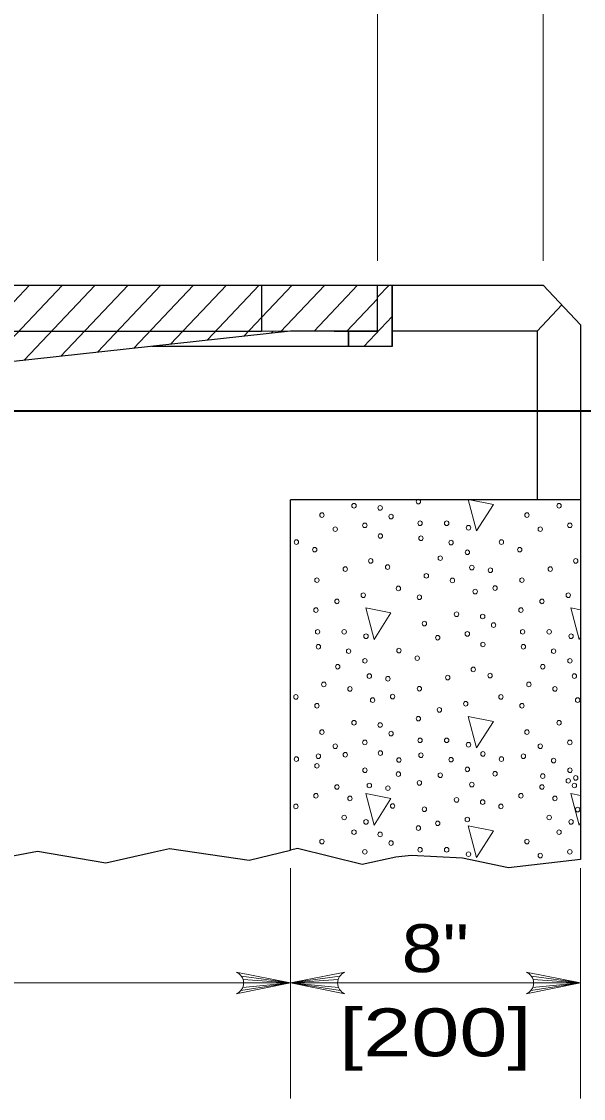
# Model space of a CAD drawing. Extents: x -410.5 to -376.5, y 1617.6 to 1661.6.
# Drawn here: x -402.554 to -400.725, y 1656.08 to 1659.586 of the extents above; entities that cross this region are included whole.
import ezdxf
from ezdxf.enums import TextEntityAlignment as Align

# ---------------------------------------------------------------- set-up
doc = ezdxf.new("R2010")
doc.units = 0
doc.header["$LTSCALE"] = 0.062
doc.layers.add('1', color=7, linetype='Continuous', lineweight=13)

msp = doc.modelspace()

# ---------------------------------------------------------------- linework, layer by layer
at = {"layer": '1'}
for p, q in [((-401.39508, 1658.80683), (-401.39508, 1659.92217)), ((-400.85642, 1658.80683), (-400.85642, 1659.92217)), ((-402.78417, 1658.457), (-402.52817, 1658.72817)), ((-402.66508, 1658.47008), (-402.42133, 1658.72817)), ((-402.54592, 1658.48317), (-402.3145, 1658.72817)), ((-402.42683, 1658.49617), (-402.20775, 1658.72817)), ((-402.30767, 1658.50925), (-402.10092, 1658.72817)), ((-402.18858, 1658.52225), (-401.99408, 1658.72817)), ((-402.06942, 1658.53533), (-401.88733, 1658.72817)), ((-401.95025, 1658.54842), (-401.7805, 1658.72817)), ((-401.89075, 1658.72817), (-401.70192, 1658.72817)), ((-401.83117, 1658.56142), (-401.67375, 1658.72817)), ((-401.71208, 1658.5745), (-401.56692, 1658.72817)), ((-401.60175, 1658.57825), (-401.46008, 1658.72817)), ((-401.39508, 1658.6885), (-401.35767, 1658.72817)), ((-401.49517, 1658.578), (-401.39525, 1658.68375)), ((-401.43975, 1658.52825), (-401.34792, 1658.62542)), ((-401.77275, 1658.57825), (-401.67833, 1658.57825)), ((-401.74208, 1658.57125), (-401.73542, 1658.57825)), ((-401.6825, 1658.57775), (-401.68208, 1658.57825)), ((-400.73442, 1657.6705), (-400.76633, 1657.67675)), ((-400.73433, 1657.06608), (-400.76633, 1657.07225)), ((-401.67833, 1656.07967), (-401.67833, 1656.82983)), ((-400.73433, 1656.07967), (-400.73433, 1656.82983)), ((-401.83858, 1656.47817), (-401.67833, 1656.45575)), ((-401.83308, 1656.46708), (-401.67833, 1656.45575)), ((-401.51808, 1656.47817), (-401.67833, 1656.45575)), ((-401.5235, 1656.46708), (-401.67833, 1656.45575)), ((-400.89458, 1656.47817), (-400.73433, 1656.45575)), ((-400.88908, 1656.46708), (-400.73433, 1656.45575)), ((-404.41592, 1656.45575), (-402.47617, 1656.45575)), ((-402.47617, 1656.45575), (-401.67833, 1656.45575)), ((-401.84042, 1656.43092), (-401.67833, 1656.45575)), ((-401.83433, 1656.44133), (-401.67833, 1656.45575)), ((-401.8315, 1656.45575), (-401.67833, 1656.45575)), ((-401.52517, 1656.45575), (-401.67833, 1656.45575)), ((-401.52233, 1656.44133), (-401.67833, 1656.45575)), ((-401.51617, 1656.43092), (-401.67833, 1656.45575)), ((-400.89642, 1656.43092), (-400.73433, 1656.45575)), ((-400.89033, 1656.44133), (-400.73433, 1656.45575)), ((-400.8875, 1656.45575), (-400.73433, 1656.45575))]:
    msp.add_line(p, q, dxfattribs=at)
at = {"layer": '1', "lineweight": 25}
for p, q in [((-401.77275, 1658.72817), (-401.77275, 1658.57825)), ((-401.39508, 1658.57825), (-401.39508, 1658.72817)), ((-401.39508, 1658.57825), (-401.39508, 1658.72817)), ((-401.34792, 1658.52825), (-401.34792, 1658.72817)), ((-401.30075, 1658.72817), (-400.85642, 1658.72817)), ((-400.73433, 1658.59883), (-400.85642, 1658.72817)), ((-400.87592, 1658.57825), (-400.79533, 1658.6635)), ((-404.3215, 1658.57825), (-401.77275, 1658.57825)), ((-401.39508, 1658.57825), (-401.55542, 1658.57825)), ((-401.4895, 1658.57825), (-401.4895, 1658.52825)), ((-400.87592, 1658.57825), (-401.34983, 1658.57825)), ((-400.87592, 1658.57825), (-400.87592, 1658.0285)), ((-400.73433, 1658.59883), (-400.73433, 1656.858)), ((-401.55542, 1658.52825), (-402.1305, 1658.52825)), ((-401.34792, 1658.52825), (-401.55542, 1658.52825)), ((-400.73433, 1658.0285), (-401.67833, 1658.0285))]:
    msp.add_line(p, q, dxfattribs=at)
at = {"layer": '1', "lineweight": 35}
msp.add_line((-405.89092, 1658.31867), (-400.23342, 1658.31867), dxfattribs=at)
at = {"layer": '1', "lineweight": 25}
for points in [[(-405.23783, 1658.72817), (-404.7935, 1658.72817), (-404.69908, 1658.72817), (-404.3215, 1658.72817), (-401.77275, 1658.72817), (-401.39508, 1658.72817), (-401.30075, 1658.72817)], [(-401.53675, 1658.57825), (-401.39508, 1658.57825), (-401.39508, 1658.72817)], [(-401.53675, 1658.57825), (-401.67833, 1658.57825), (-403.04708, 1658.42833), (-404.41592, 1658.57825), (-404.5575, 1658.57825)], [(-400.73433, 1656.858), (-400.96875, 1656.83008), (-401.11925, 1656.86183), (-401.286, 1656.87042), (-401.33525, 1656.86542), (-401.44525, 1656.8415), (-401.65542, 1656.89367), (-401.67833, 1656.88817), (-401.67833, 1658.0285)], [(-404.41592, 1656.87183), (-404.2725, 1656.83983), (-404.153, 1656.87083), (-403.98442, 1656.85217), (-403.92575, 1656.855), (-403.82517, 1656.88925), (-403.76458, 1656.882), (-403.7105, 1656.87983), (-403.49083, 1656.84083), (-403.33433, 1656.88892), (-403.13075, 1656.86817), (-402.962, 1656.90217), (-402.852, 1656.909), (-402.67125, 1656.85375), (-402.5025, 1656.88475), (-402.27992, 1656.84675), (-402.12158, 1656.88275), (-402.07225, 1656.89375), (-401.81283, 1656.85558), (-401.67833, 1656.88817)]]:
    msp.add_lwpolyline(points, dxfattribs=at)
msp.add_lwpolyline([(-401.4895, 1658.57825), (-401.39508, 1658.57825), (-401.39508, 1658.72817), (-401.34792, 1658.72817), (-401.34792, 1658.52825), (-401.4895, 1658.52825)], close=True, dxfattribs=at)
at = {"layer": '1'}
for points in [[(-401.1, 1658.03008), (-401.07308, 1657.92767), (-401.01817, 1658.01408)], [(-401.43383, 1657.67675), (-401.40683, 1657.57442), (-401.35183, 1657.66083)], [(-401.1, 1657.32342), (-401.07308, 1657.221), (-401.01817, 1657.30742)], [(-401.43383, 1657.07225), (-401.40683, 1656.96983), (-401.35183, 1657.05625)], [(-401.1, 1656.96708), (-401.07308, 1656.86467), (-401.01817, 1656.95117)]]:
    msp.add_lwpolyline(points, close=True, dxfattribs=at)
for points in [[(-400.76633, 1657.67675), (-400.73933, 1657.57442), (-400.73433, 1657.58217)], [(-400.76633, 1657.07225), (-400.73933, 1656.96983), (-400.73433, 1656.97792)], [(-401.85533, 1656.42033), (-401.67833, 1656.45575), (-401.85533, 1656.49108)], [(-401.50133, 1656.42033), (-401.67833, 1656.45575), (-401.50133, 1656.49108)], [(-400.91133, 1656.42033), (-400.73433, 1656.45575), (-400.91133, 1656.49108)], [(-401.67833, 1656.45575), (-400.9465, 1656.45575), (-400.73433, 1656.45575)]]:
    msp.add_lwpolyline(points, dxfattribs=at)
for centre, start, end in [((-401.86959, 1656.45576), 292.08605, 67.91218), ((-401.48701, 1656.45576), 112.08782, 247.91395), ((-400.92559, 1656.45576), 292.08605, 67.91218)]:
    msp.add_arc(centre, 0.0382, start, end, dxfattribs=at)
for centre, major_axis in [((-401.47193, 1658.00974), (0, 0.00756)), ((-401.38687, 1658.00238), (0, 0.00756)), ((-401.26222, 1658.02305), (0, -0.00756)), ((-400.80442, 1658.00974), (0, 0.00756)), ((-401.57645, 1657.97918), (0, 0.00756)), ((-401.35144, 1657.97441), (0, -0.00756)), ((-400.90894, 1657.97918), (0, 0.00756)), ((-401.53317, 1657.93336), (0, 0.00756)), ((-401.43677, 1657.94579), (0, 0.00756)), ((-401.25682, 1657.95244), (0, -0.00756)), ((-401.17027, 1657.95244), (0, 0.00756)), ((-401.09912, 1657.93813), (0, -0.00756)), ((-400.86566, 1657.93336), (0, 0.00756)), ((-400.76926, 1657.94579), (0, 0.00756)), ((-401.65938, 1657.89137), (0, -0.00756)), ((-401.38598, 1657.9111), (0, -0.00756)), ((-401.25415, 1657.9038), (0, -0.00756)), ((-400.99188, 1657.89137), (0, -0.00756)), ((-401.59992, 1657.86658), (0, -0.00756)), ((-401.15586, 1657.88949), (0, 0.00756)), ((-401.10274, 1657.85798), (0, 0.00756)), ((-400.93241, 1657.86658), (0, -0.00756)), ((-401.41752, 1657.83), (0, -0.00756)), ((-401.19107, 1657.8389), (0, 0.00756)), ((-400.75001, 1657.83), (0, -0.00756)), ((-401.50046, 1657.80333), (0, -0.00756)), ((-401.36257, 1657.80998), (0, -0.00756)), ((-401.08827, 1657.80839), (0, 0.00756)), ((-401.02792, 1657.79973), (0, -0.00756)), ((-400.83295, 1657.80333), (0, -0.00756)), ((-401.59269, 1657.76728), (0, -0.00756)), ((-401.23641, 1657.78136), (0, 0.00756)), ((-401.15141, 1657.7664), (0, 0.00756)), ((-400.92518, 1657.76728), (0, -0.00756)), ((-401.44189, 1657.71835), (0, -0.00756)), ((-401.32747, 1657.74031), (0, 0.00756)), ((-401.07754, 1657.73012), (0, 0.00756)), ((-401.01262, 1657.74161), (0, -0.00756)), ((-400.77438, 1657.71835), (0, -0.00756)), ((-401.52755, 1657.69832), (0, -0.00756)), ((-401.25893, 1657.71169), (0, 0.00756)), ((-400.86004, 1657.69832), (0, -0.00756)), ((-401.59597, 1657.6697), (0, -0.00756)), ((-401.13817, 1657.65639), (0, 0.00756)), ((-401.05312, 1657.64903), (0, 0.00756)), ((-400.92846, 1657.6697), (0, -0.00756)), ((-401.24269, 1657.62583), (0, 0.00756)), ((-401.01769, 1657.62106), (0, -0.00756)), ((-401.59058, 1657.59909), (0, -0.00756)), ((-401.50402, 1657.59909), (0, 0.00756)), ((-401.43288, 1657.58478), (0, -0.00756)), ((-401.19942, 1657.58001), (0, 0.00756)), ((-401.10302, 1657.59244), (0, 0.00756)), ((-400.92307, 1657.59909), (0, -0.00756)), ((-400.83651, 1657.59909), (0, 0.00756)), ((-400.76537, 1657.58478), (0, -0.00756)), ((-401.58791, 1657.55045), (0, -0.00756)), ((-401.05223, 1657.55775), (0, -0.00756)), ((-400.9204, 1657.55045), (0, -0.00756)), ((-401.48961, 1657.53614), (0, 0.00756)), ((-401.32563, 1657.53802), (0, -0.00756)), ((-401.26617, 1657.51323), (0, -0.00756)), ((-400.82211, 1657.53614), (0, 0.00756)), ((-401.52483, 1657.48555), (0, 0.00756)), ((-401.43649, 1657.50463), (0, 0.00756)), ((-401.08377, 1657.47665), (0, -0.00756)), ((-400.85732, 1657.48555), (0, 0.00756)), ((-400.76898, 1657.50463), (0, 0.00756)), ((-401.42203, 1657.45504), (0, 0.00756)), ((-401.36168, 1657.44638), (0, -0.00756)), ((-401.16671, 1657.44998), (0, -0.00756)), ((-401.02881, 1657.45663), (0, -0.00756)), ((-400.75452, 1657.45504), (0, 0.00756)), ((-401.57016, 1657.42801), (0, 0.00756)), ((-401.48516, 1657.41305), (0, 0.00756)), ((-401.25893, 1657.41394), (0, -0.00756)), ((-400.90265, 1657.42801), (0, 0.00756)), ((-400.81766, 1657.41305), (0, 0.00756)), ((-401.66122, 1657.38696), (0, 0.00756)), ((-401.41129, 1657.37677), (0, 0.00756)), ((-401.34638, 1657.38826), (0, -0.00756)), ((-401.10813, 1657.365), (0, -0.00756)), ((-400.99371, 1657.38696), (0, 0.00756)), ((-400.74378, 1657.37677), (0, 0.00756)), ((-401.59269, 1657.35834), (0, 0.00756)), ((-401.1938, 1657.34497), (0, -0.00756)), ((-400.92518, 1657.35834), (0, 0.00756)), ((-401.47193, 1657.30304), (0, 0.00756)), ((-401.38687, 1657.29568), (0, 0.00756)), ((-401.26222, 1657.31635), (0, -0.00756)), ((-400.80442, 1657.30304), (0, 0.00756)), ((-401.57645, 1657.27248), (0, 0.00756)), ((-401.35144, 1657.26771), (0, -0.00756)), ((-400.90894, 1657.27248), (0, 0.00756)), ((-401.53317, 1657.22666), (0, 0.00756)), ((-401.43677, 1657.23909), (0, 0.00756)), ((-401.25682, 1657.24574), (0, -0.00756)), ((-401.17027, 1657.24574), (0, 0.00756)), ((-401.09912, 1657.23143), (0, -0.00756)), ((-400.86566, 1657.22666), (0, 0.00756)), ((-400.76926, 1657.23909), (0, 0.00756)), ((-401.58791, 1657.19412), (0, -0.00756)), ((-401.50046, 1657.19882), (0, -0.00756)), ((-401.38598, 1657.2044), (0, -0.00756)), ((-401.25415, 1657.1971), (0, -0.00756)), ((-401.05223, 1657.20143), (0, -0.00756)), ((-400.9204, 1657.19412), (0, -0.00756)), ((-401.65938, 1657.18467), (0, -0.00756)), ((-401.59269, 1657.16278), (0, -0.00756)), ((-401.32563, 1657.1817), (0, -0.00756)), ((-401.15586, 1657.18279), (0, 0.00756)), ((-400.99188, 1657.18467), (0, -0.00756)), ((-400.82211, 1657.17981), (0, 0.00756)), ((-401.43649, 1657.14831), (0, 0.00756)), ((-401.32747, 1657.13581), (0, 0.00756)), ((-401.19107, 1657.1322), (0, 0.00756)), ((-401.10274, 1657.15128), (0, 0.00756)), ((-401.01262, 1657.1371), (0, -0.00756)), ((-400.85732, 1657.12923), (0, 0.00756)), ((-400.76898, 1657.14831), (0, 0.00756)), ((-400.75001, 1657.1233), (0, -0.00756)), ((-401.52755, 1657.09382), (0, -0.00756)), ((-401.42203, 1657.09872), (0, 0.00756)), ((-401.36168, 1657.09006), (0, -0.00756)), ((-401.25894, 1657.10719), (0, 0.00756)), ((-401.08827, 1657.10169), (0, 0.00756)), ((-400.86004, 1657.09382), (0, -0.00756)), ((-400.77438, 1657.11384), (0, -0.00756)), ((-400.75452, 1657.09872), (0, 0.00756)), ((-401.59597, 1657.0652), (0, -0.00756)), ((-401.48517, 1657.05673), (0, 0.00756)), ((-401.13817, 1657.05189), (0, 0.00756)), ((-400.92846, 1657.0652), (0, -0.00756)), ((-400.81766, 1657.05673), (0, 0.00756)), ((-401.66122, 1657.03064), (0, 0.00756)), ((-401.34638, 1657.03194), (0, -0.00756)), ((-401.24269, 1657.02132), (0, 0.00756)), ((-401.05312, 1657.04453), (0, 0.00756)), ((-400.99371, 1657.03064), (0, 0.00756)), ((-400.74379, 1657.02045), (0, 0.00756)), ((-401.50402, 1656.99459), (0, 0.00756)), ((-401.43288, 1656.98028), (0, -0.00756)), ((-401.10302, 1656.98793), (0, 0.00756)), ((-400.83651, 1656.99459), (0, 0.00756)), ((-400.76537, 1656.98028), (0, -0.00756)), ((-401.47193, 1656.94672), (0, 0.00756)), ((-401.26222, 1656.96003), (0, -0.00756)), ((-401.19942, 1656.9755), (0, 0.00756)), ((-400.80442, 1656.94672), (0, 0.00756)), ((-401.57645, 1656.91616), (0, 0.00756)), ((-401.38688, 1656.93936), (0, 0.00756)), ((-401.35144, 1656.91139), (0, -0.00756)), ((-400.90894, 1656.91616), (0, 0.00756)), ((-401.43677, 1656.88276), (0, 0.00756)), ((-401.25682, 1656.88942), (0, -0.00756)), ((-401.17027, 1656.88942), (0, 0.00756)), ((-401.09912, 1656.87511), (0, -0.00756)), ((-400.76926, 1656.88276), (0, 0.00756)), ((-400.86566, 1656.87034), (0, 0.00756))]:
    msp.add_ellipse(centre, major_axis=major_axis, ratio=0.944543, dxfattribs=at)

# ---------------------------------------------------------------- texts
for s, width, p in [('8"', 1.15, (-401.20725, 1656.49092)), ('[200]', 1.35, (-401.20725, 1656.21692))]:
    msp.add_text(s, height=0.156, dxfattribs=dict(at, width=width)).set_placement(p, align=Align.CENTER)

doc.saveas('drawing.dxf')
